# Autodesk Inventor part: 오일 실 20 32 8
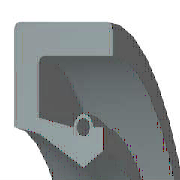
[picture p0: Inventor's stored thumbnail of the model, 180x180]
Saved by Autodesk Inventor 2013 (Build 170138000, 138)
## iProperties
IsCustomPart: 1
Created: 2012-02
Part Number: 오일 실 20 32 8
Material: 고무
Description: 오일 실 - 스프링 장착, 금속 케이스 SM
Document SubType Name: Modeling
Standard: JIS B 2402
Designer: mdu-01
Standards Organization: JIS
Language: ko-KR
Size Designation: 20 32 8 A
Categories: <MemberInstance><Categories><Category DisplayName="샤프트 부품" InternalName="7f7aeb1f-a693-4053-b835-cee3144e0d98" Mnemonic="SHFT"><Category DisplayName="실링" Intern
Density: 0.93 g/cm^3
Author: mdu-01
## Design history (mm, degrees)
body "Solid1"
revolve "회전1" stored, may be unused: angle "d33" = 360 deg
fillet "모깎기1" dims "d34" = 0.4 (= 0.05 x b)
chamfer "모따기1" distance "d35" = 0.8 (= 0.1 x b); stored, may be unused: second distance "d36" = 0.4 (= 0.05 x b), angle "d41" = 45 deg
sketch "스케치2"
  geometry: L1 (11.457, -5.895)-(12.021, -8); L2 (10.857, -5.2)-(11.457, -5.895); L3 (10, -2)-(10.857, -5.2); L4 (10.8, -1)-(10, -2); L5 (12.141, -1)-(10.8, -1); L6 (12.141, -1.8)-(12.141, -1); L7 (12.141, -6)-(12.141, -3.4); L8 (13.6, -6)-(12.141, -6); L9 (14.8, -2)-(13.6, -6); L10 (14.8, 0)-(14.8, -2); L11 (16, 0)-(14.8, 0); L12 (16, -8)-(16, 0); L13 (12.021, -8)-(16, -8); L14 (0, -9.6)-(0, 1.6) reference; L15 (28, 0)-(14, 0) reference; A1 r 0.8 centre (12.141, -2.6) between (12.141, -3.4) and (12.141, -1.8)
  constraints: 26 end point, 4 horizontal, 4 vertical, 2 point on circle, 1 centre point, 1 collinear, 1 parallel
  dimensions: "d2" = 8 distance of L12.start L11.start (= b); "d4" = 1 vertical distance of L10.start L5.start (= 0.125 x b); "d6" = 1.2 distance of L11.start L10.start (= 0.1 x dd - 0.1 x Diam); "d8" = 2 distance of L10.start L9.start (= 0.25 x b); "d10" = 2 vertical distance of L8.start L1.end (= 0.25 x b); "d12" = 1.2 horizontal distance of L9.start L8.start (= 0.1 x dd - 0.1 x Diam); "d14" = 0.8 radius of A1 (= 0.1 x b); "d16" = 0 horizontal distance of A1.centre L7.end; "d18" = 0.8 distance of L6.start L5.start (= 0.1 x b); "d20" = 0.8 horizontal distance of L4.start L3.start (= 0.0666667 x dd - 0.0666667 x Diam); "d22" = 0.12 horizontal distance of L7.start L1.end (= 0.01 x dd - 0.01 x Diam); "d24" = 1 vertical distance of L4.start L3.start (= 0.125 x b); "d26" = 3.2 vertical distance of L3.start L2.start (= 0.4 x b); "d28" = 0.85714 horizontal distance of L3.start L2.start (= 0.0714286 x dd - 0.0714286 x Diam); "d30" = 2.10526 vertical distance of L1.start L1.end (= 0.263158 x b); "d32" = 0.6 horizontal distance of L2.start L1.start (= 0.05 x dd - 0.05 x Diam); "d37" = 0 distance between parallel lines of L15 L11; "d38" = 16 distance between parallel lines of L14 L12 (= 0.5 x dd); "d39" = 10 distance from line of L14 L3.start (= 0.5 x Diam)
other parameters: "dd" = 32 [user parameter; used in 7 equation terms], "b" = 8 [user parameter; used in 12 equation terms], "d1" = 8 (derived), "d3" = 1 (derived), "d5" = 2 (derived), "d7" = 2 (derived), "d9" = 2 (derived), "d11" = 2 (derived), "d13" = 0.8 (derived), "d15" = 0 (derived), "d17" = 0.8 (derived), "d19" = 1.33333 (derived), "d21" = 0.2 (derived), "d23" = 1 (derived), "d25" = 3.2 (derived), "d27" = 1.42857 (derived), "d29" = 2.10526 (derived), "d31" = 1 (derived), "d40" = 0
